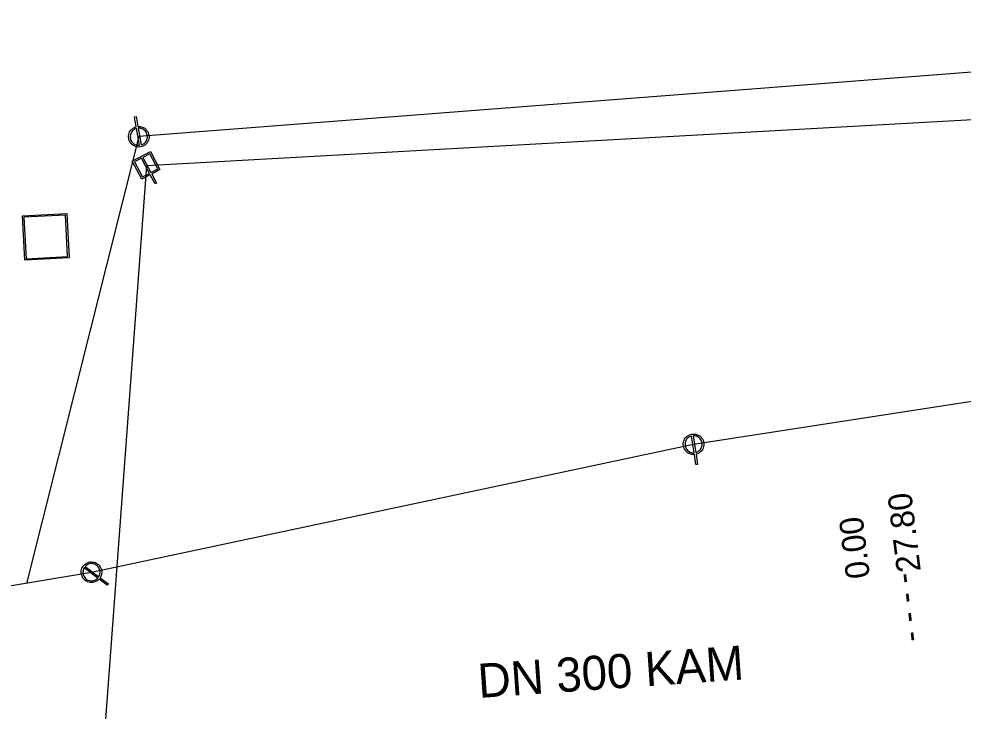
# Model space of a CAD drawing. Extents: x -818321 to -817653, y -1049725 to -1049329.
# Drawn here: x -817742.06 to -817714.4, y -1049380.87 to -1049360.59 of the extents above; entities that cross this region are included whole.
import ezdxf

# ---------------------------------------------------------------- set-up
doc = ezdxf.new("R2010")
doc.units = 0
doc.layers.add('Default', color=7, linetype='Continuous')
doc.layers.add('Level 0', color=7, linetype='Continuous')

msp = doc.modelspace()

# ---------------------------------------------------------------- linework, layer by layer
at = {"layer": 'Default'}
for points in [[(-817738.623, -1049363.75), (-817738.676, -1049363.454), (-817738.627, -1049363.445), (-817738.575, -1049363.741)], [(-817738.566, -1049363.791), (-817738.48, -1049364.281)], [(-817738.528, -1049364.29), (-817738.614, -1049363.8)], [(-817738.169, -1049365.133), (-817738.028, -1049365.398), (-817738.072, -1049365.421), (-817738.212, -1049365.156), (-817738.456, -1049365.285), (-817738.737, -1049364.755), (-817738.207, -1049364.474), (-817737.926, -1049365.003), (-817738.169, -1049365.133)], [(-817738.192, -1049365.089), (-817737.992, -1049364.983), (-817738.228, -1049364.54), (-817738.427, -1049364.646), (-817738.192, -1049365.089)], [(-817738.235, -1049365.112), (-817738.471, -1049364.669), (-817738.671, -1049364.776), (-817738.435, -1049365.218), (-817738.235, -1049365.112)], [(-817740.591, -1049367.592), (-817741.889, -1049367.66), (-817741.957, -1049366.361), (-817740.659, -1049366.293), (-817740.591, -1049367.592)], [(-817740.697, -1049366.336), (-817741.914, -1049366.4), (-817741.851, -1049367.617), (-817740.634, -1049367.553), (-817740.697, -1049366.336)], [(-817722.279, -1049373.3), (-817722.357, -1049372.809)], [(-817722.308, -1049372.801), (-817722.231, -1049373.292)], [(-817722.223, -1049373.343), (-817722.176, -1049373.64), (-817722.224, -1049373.647), (-817722.271, -1049373.35)], [(-817739.75, -1049376.969), (-817740.147, -1049376.67)], [(-817740.117, -1049376.63), (-817739.72, -1049376.93)], [(-817739.679, -1049376.96), (-817739.439, -1049377.141), (-817739.469, -1049377.181), (-817739.709, -1049377)]]:
    msp.add_lwpolyline(points, dxfattribs=at)
for points in [[(-817738.575, -1049363.741), (-817738.513, -1049363.734), (-817738.445, -1049363.758), (-817738.368, -1049363.784), (-817738.317, -1049363.848), (-817738.265, -1049363.911), (-817738.252, -1049363.988), (-817738.238, -1049364.065), (-817738.265, -1049364.143), (-817738.293, -1049364.221), (-817738.356, -1049364.272), (-817738.42, -1049364.322), (-817738.495, -1049364.336), (-817738.569, -1049364.349), (-817738.647, -1049364.323), (-817738.724, -1049364.297), (-817738.777, -1049364.234), (-817738.829, -1049364.17), (-817738.843, -1049364.092), (-817738.856, -1049364.015), (-817738.83, -1049363.938), (-817738.803, -1049363.861), (-817738.739, -1049363.81), (-817738.684, -1049363.764), (-817738.623, -1049363.75)], [(-817738.48, -1049364.281), (-817738.434, -1049364.269), (-817738.388, -1049364.233), (-817738.334, -1049364.191), (-817738.312, -1049364.126), (-817738.289, -1049364.061), (-817738.301, -1049363.997), (-817738.312, -1049363.933), (-817738.355, -1049363.88), (-817738.397, -1049363.827), (-817738.462, -1049363.806), (-817738.517, -1049363.786), (-817738.566, -1049363.791)], [(-817738.614, -1049363.8), (-817738.662, -1049363.812), (-817738.708, -1049363.849), (-817738.761, -1049363.892), (-817738.783, -1049363.956), (-817738.805, -1049364.02), (-817738.793, -1049364.084), (-817738.782, -1049364.148), (-817738.739, -1049364.201), (-817738.695, -1049364.254), (-817738.631, -1049364.276), (-817738.576, -1049364.294), (-817738.528, -1049364.29)], [(-817722.271, -1049373.35), (-817722.333, -1049373.356), (-817722.401, -1049373.331), (-817722.477, -1049373.304), (-817722.528, -1049373.239), (-817722.578, -1049373.175), (-817722.59, -1049373.098), (-817722.602, -1049373.02), (-817722.574, -1049372.943), (-817722.545, -1049372.865), (-817722.481, -1049372.816), (-817722.416, -1049372.766), (-817722.341, -1049372.755), (-817722.266, -1049372.743), (-817722.189, -1049372.77), (-817722.112, -1049372.797), (-817722.061, -1049372.862), (-817722.01, -1049372.926), (-817721.998, -1049373.004), (-817721.985, -1049373.081), (-817722.013, -1049373.158), (-817722.041, -1049373.234), (-817722.106, -1049373.284), (-817722.162, -1049373.329), (-817722.223, -1049373.343)], [(-817722.357, -1049372.809), (-817722.403, -1049372.82), (-817722.45, -1049372.855), (-817722.504, -1049372.897), (-817722.528, -1049372.961), (-817722.551, -1049373.026), (-817722.541, -1049373.09), (-817722.531, -1049373.154), (-817722.489, -1049373.208), (-817722.447, -1049373.261), (-817722.383, -1049373.284), (-817722.328, -1049373.304), (-817722.279, -1049373.3)], [(-817722.231, -1049373.292), (-817722.183, -1049373.281), (-817722.136, -1049373.245), (-817722.083, -1049373.203), (-817722.06, -1049373.14), (-817722.037, -1049373.076), (-817722.047, -1049373.012), (-817722.057, -1049372.947), (-817722.1, -1049372.893), (-817722.142, -1049372.839), (-817722.206, -1049372.817), (-817722.261, -1049372.798), (-817722.308, -1049372.801)], [(-817739.709, -1049377), (-817739.75, -1049377.047), (-817739.815, -1049377.076), (-817739.89, -1049377.109), (-817739.971, -1049377.098), (-817740.051, -1049377.086), (-817740.114, -1049377.039), (-817740.176, -1049376.992), (-817740.21, -1049376.917), (-817740.243, -1049376.841), (-817740.231, -1049376.761), (-817740.219, -1049376.68), (-817740.173, -1049376.619), (-817740.127, -1049376.559), (-817740.053, -1049376.525), (-817739.979, -1049376.491), (-817739.897, -1049376.502), (-817739.815, -1049376.513), (-817739.753, -1049376.56), (-817739.69, -1049376.607), (-817739.657, -1049376.682), (-817739.624, -1049376.756), (-817739.635, -1049376.837), (-817739.645, -1049376.908), (-817739.679, -1049376.96)], [(-817740.147, -1049376.67), (-817740.172, -1049376.71), (-817740.181, -1049376.768), (-817740.191, -1049376.835), (-817740.164, -1049376.898), (-817740.136, -1049376.961), (-817740.084, -1049377), (-817740.032, -1049377.039), (-817739.965, -1049377.048), (-817739.898, -1049377.058), (-817739.836, -1049377.03), (-817739.782, -1049377.006), (-817739.75, -1049376.969)], [(-817739.72, -1049376.93), (-817739.693, -1049376.888), (-817739.685, -1049376.83), (-817739.676, -1049376.763), (-817739.703, -1049376.701), (-817739.731, -1049376.639), (-817739.783, -1049376.6), (-817739.835, -1049376.561), (-817739.903, -1049376.552), (-817739.971, -1049376.542), (-817740.033, -1049376.571), (-817740.085, -1049376.595), (-817740.117, -1049376.63)]]:
    msp.add_open_spline(points, degree=3, dxfattribs=at)
at = {"layer": 'Level 0'}
for p, q in [((-817694.05, -1049360.586), (-817738.548, -1049364.035)), ((-817713.605, -1049363.519), (-817738.325, -1049364.887)), ((-817738.548, -1049364.035), (-817741.841, -1049377.126)), ((-817738.325, -1049364.887), (-817739.683, -1049383.281)), ((-817704.253, -1049370.276), (-817722.293, -1049373.056)), ((-817722.293, -1049373.056), (-817739.929, -1049376.803)), ((-817739.929, -1049376.803), (-817767.788, -1049381.512))]:
    msp.add_line(p, q, dxfattribs=at)

# ---------------------------------------------------------------- texts
for s, height, rotation, p in [('27.80', 0.7, 97, (-817715.635, -1049376.761)), ('0.00', 0.7, 97, (-817717.123, -1049376.947)), ('- - - -', 0.7, 277, (-817716.379, -1049376.854)), ('DN 300 KAM', 1, 4, (-817728.58, -1049380.484))]:
    msp.add_text(s, height=height, rotation=rotation, dxfattribs=at).set_placement(p)

doc.saveas('drawing.dxf')
